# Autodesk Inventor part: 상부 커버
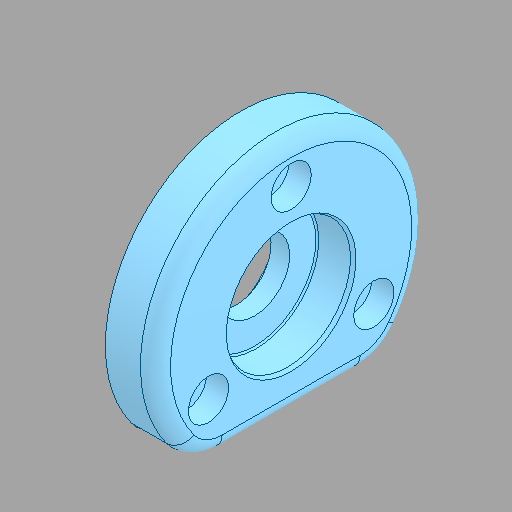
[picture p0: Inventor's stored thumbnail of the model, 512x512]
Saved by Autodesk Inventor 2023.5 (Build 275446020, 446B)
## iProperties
Created: 2026-03
Part Number: 상부 커버
Material: 알루미늄 6061
Document SubType Name: Modeling
Designer: mirae
Density: 2.7 g/cm^3
Appearance: 기본값
Author: jhkim
Sending System: Autodesk Inventor 2026
Preprocessor: ST-DEVELOPER v20.1
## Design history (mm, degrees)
node "상부 커버1"
node "솔리드2"
node "솔리드1"
